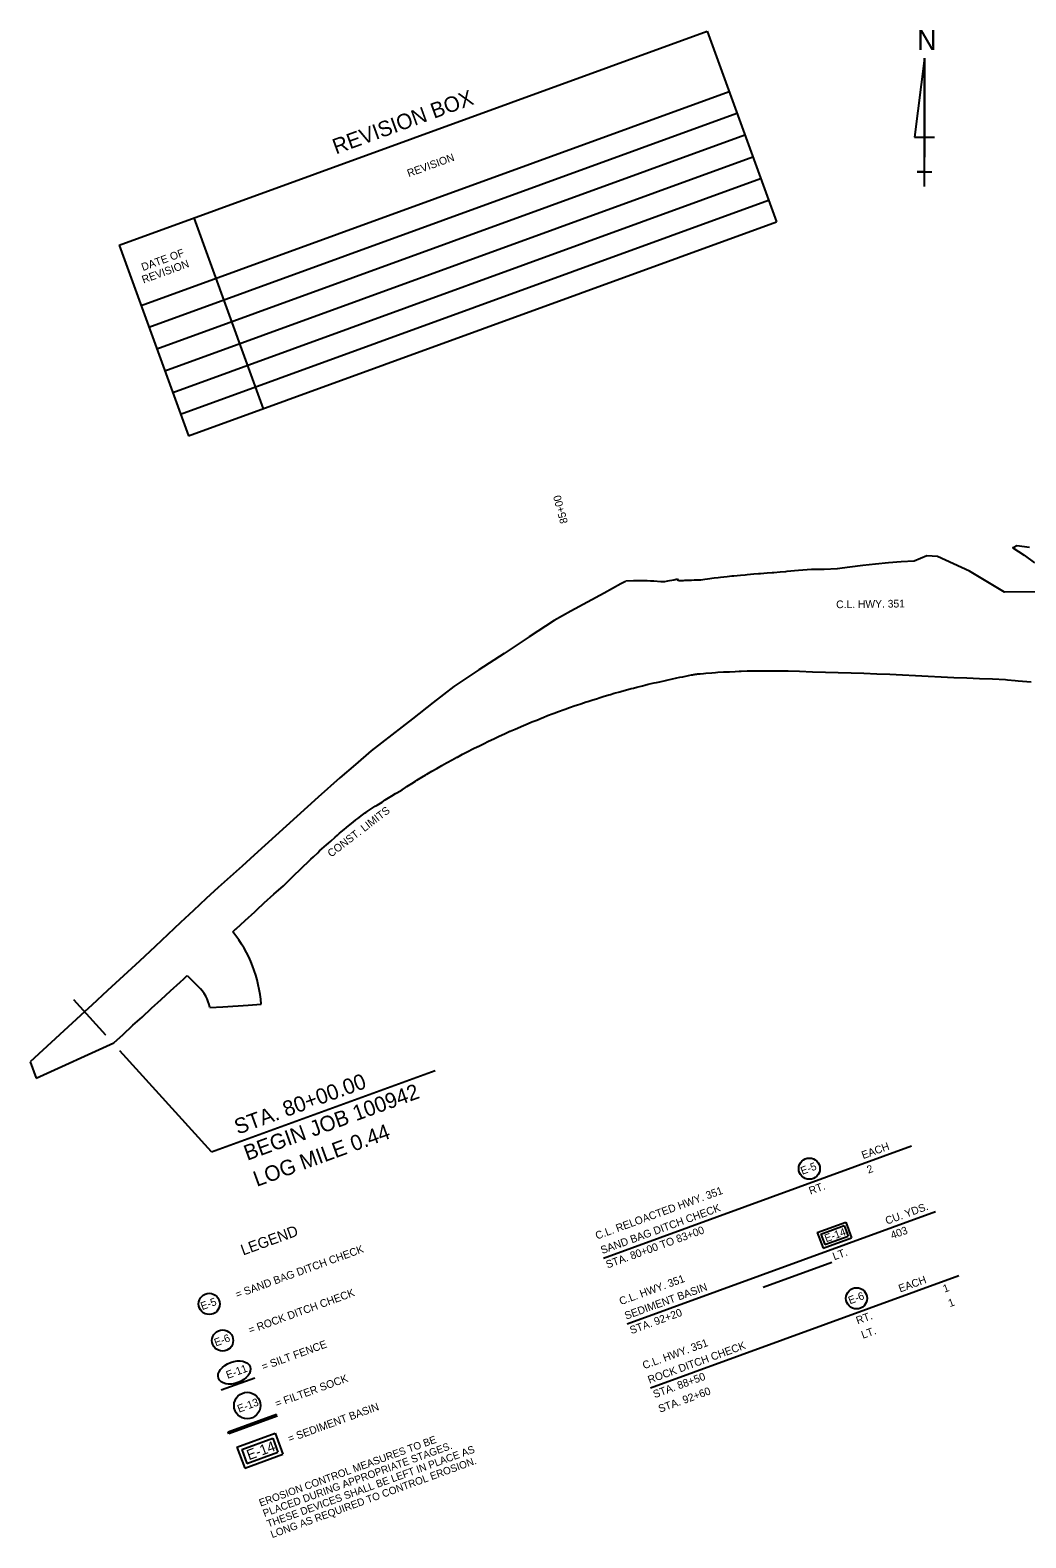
# Model space of a CAD drawing. Extents: x 1710803 to 1712425, y 548489 to 549912.
# Drawn here: x 1710803 to 1711577, y 548489 to 549662 of the extents above; entities that cross this region are included whole.
import ezdxf

# ---------------------------------------------------------------- set-up
doc = ezdxf.new("R2010")
doc.units = 0
for name, color, linetype in [('Default', 7, 'Continuous'), ('R_Contour Annot', 7, 'Continuous'), ('R_Contours', 7, 'Continuous'), ('R_Erosion', 7, 'Continuous'), ('R_Horz Alg', 7, 'Continuous'), ('R_Horz Alg Annot', 7, 'Continuous')]:
    doc.layers.add(name, color=color, linetype=linetype)

msp = doc.modelspace()

# ---------------------------------------------------------------- linework, layer by layer
at = {"layer": 'Default'}
msp.add_line((1711373, 548683.8), (1711426.2, 548703.2), dxfattribs=at)
at = {"layer": 'R_Contour Annot'}
for p, q in [((1711498.4, 549640), (1711490.7, 549578.4)), ((1711498.4, 549540), (1711498.4, 549640)), ((1711498.4, 549640), (1711498.4, 549563)), ((1711490.7, 549578.4), (1711506.1, 549578.4)), ((1711498.4, 549540), (1711498.4, 549563)), ((1711498.4, 549551.5), (1711492.7, 549551.5)), ((1711492.7, 549551.5), (1711504.2, 549551.5)), ((1711498.4, 549540), (1711498.4, 549551.5))]:
    msp.add_line(p, q, dxfattribs=at)
at = {"layer": 'R_Contours'}
for p, q in [((1710871.8, 549494.5), (1711329.2, 549661)), ((1711329.2, 549661), (1711383.3, 549512.5)), ((1710888.9, 549447.5), (1711346.3, 549614)), ((1710895, 549430.6), (1711352.5, 549597.1)), ((1710901.2, 549413.7), (1711358.6, 549580.2)), ((1710907.3, 549396.8), (1711364.8, 549563.3)), ((1710913.5, 549379.9), (1711370.9, 549546.4)), ((1710919.7, 549362.9), (1711377.1, 549529.4)), ((1710929.9, 549515.6), (1710983.9, 549367.2)), ((1710925.8, 549346), (1711383.3, 549512.5)), ((1710871.8, 549494.5), (1710925.8, 549346)), ((1710943.6, 548788.9), (1711117.8, 548852.3)), ((1711248.6, 548706.3), (1711488.4, 548793.6)), ((1711267.1, 548655.3), (1711507, 548742.6)), ((1711415, 548726.3), (1711437.2, 548734.4)), ((1711417.8, 548725), (1711435.9, 548731.6)), ((1711435.9, 548731.6), (1711438.9, 548723.4)), ((1711437.2, 548734.4), (1711441.7, 548722.1)), ((1711415, 548726.3), (1711419.5, 548714)), ((1711417.8, 548725), (1711420.8, 548716.8)), ((1711419.5, 548714), (1711441.7, 548722.1)), ((1711420.8, 548716.8), (1711438.9, 548723.4)), ((1711285.3, 548605.5), (1711525.1, 548692.8))]:
    msp.add_line(p, q, dxfattribs=at)
for points in [[(1710861.5, 548879.7), (1710836.5, 548907.3)], [(1710861.5, 548879.7), (1710861.5, 548879.7)], [(1710872.4, 548867.6), (1710872.4, 548867.6)], [(1710943.6, 548788.9), (1710872.4, 548867.6)]]:
    msp.add_lwpolyline(points, dxfattribs=at)
at = {"layer": 'R_Erosion'}
for p, q in [((1710956.7, 548571.1), (1710994.3, 548584.8)), ((1710994.8, 548583.4), (1710957.2, 548569.7)), ((1710965.5, 548572.7), (1710966.4, 548574.6)), ((1710966.8, 548573.2), (1710967.7, 548575.1)), ((1710968.1, 548573.7), (1710969, 548575.6)), ((1710969.5, 548574.1), (1710970.4, 548576.1)), ((1710970.8, 548574.6), (1710971.7, 548576.5)), ((1710972.1, 548575.1), (1710973, 548577)), ((1710973.5, 548575.6), (1710974.3, 548577.5)), ((1710974.8, 548576.1), (1710975.7, 548578)), ((1710976.1, 548576.6), (1710977, 548578.5)), ((1710977.4, 548577), (1710978.3, 548579)), ((1710978.8, 548577.5), (1710979.7, 548579.4)), ((1710980.1, 548578), (1710981, 548579.9)), ((1710981.4, 548578.5), (1710982.3, 548580.4)), ((1710982.8, 548579), (1710983.7, 548580.9)), ((1710984.1, 548579.5), (1710985, 548581.4)), ((1710985.4, 548579.9), (1710986.3, 548581.9)), ((1710986.7, 548580.4), (1710987.6, 548582.3)), ((1710988.1, 548580.9), (1710989, 548582.8)), ((1710989.4, 548581.4), (1710990.3, 548583.3)), ((1710990.7, 548581.9), (1710991.6, 548583.8)), ((1710992.1, 548582.4), (1710993, 548584.3)), ((1710993.4, 548582.8), (1710994.3, 548584.8)), ((1710994.7, 548583.3), (1710994.8, 548583.5)), ((1710957.2, 548569.7), (1710956.7, 548571.1)), ((1710956.8, 548570.7), (1710957.1, 548571.2)), ((1710957.5, 548569.8), (1710958.4, 548571.7)), ((1710958.8, 548570.3), (1710959.7, 548572.2)), ((1710960.2, 548570.7), (1710961.1, 548572.7)), ((1710961.5, 548571.2), (1710962.4, 548573.2)), ((1710962.8, 548571.7), (1710963.7, 548573.6)), ((1710963.5, 548559.3), (1710993.2, 548570.1)), ((1710964.1, 548572.2), (1710965, 548574.1)), ((1710967.3, 548557.5), (1710991.5, 548566.3)), ((1710991.5, 548566.3), (1710995.4, 548555.4)), ((1710993.2, 548570.1), (1710999.2, 548553.7)), ((1710963.5, 548559.3), (1710969.5, 548542.8)), ((1710967.3, 548557.5), (1710971.3, 548546.6)), ((1710969.5, 548542.8), (1710999.2, 548553.7)), ((1710971.3, 548546.6), (1710995.4, 548555.4))]:
    msp.add_line(p, q, dxfattribs=at)
msp.add_lwpolyline([(1710951.3, 548603.7), (1710977.5, 548613.2)], dxfattribs=at)
for centre, radius in [((1711408.8, 548775.9), 8.26), ((1711445.5, 548675), 8.26), ((1710941.9, 548670.7), 8.26), ((1710952.3, 548642.2), 8.26), ((1710971.5, 548591.6), 10.3)]:
    msp.add_circle(centre, radius, dxfattribs=at)
msp.add_ellipse((1710961.4, 548617.3), major_axis=(12.3, 4.5), ratio=0.638788, dxfattribs=at)
at = {"layer": 'R_Horz Alg'}
for p, q in [((1711500.2, 549252.7), (1711490.3, 549248.7)), ((1711307.1, 549233.3), (1711306.3, 549234.5)), ((1710924.8, 548926.2), (1710933.4, 548917.6)), ((1710952.4, 548901.9), (1710972.3, 548903.2)), ((1710972.3, 548903.2), (1710982.3, 548903.9)), ((1710942.4, 548901.2), (1710952.4, 548901.9))]:
    msp.add_line(p, q, dxfattribs=at)
for points in [[(1711580.2, 549259.3), (1711570.2, 549260.4), (1711567.8, 549259.1), (1711567.2, 549258.9), (1711576, 549253.3), (1711584, 549247.3)], [(1711490.3, 549248.7), (1711480.3, 549248.2), (1711470.3, 549247.2), (1711460.3, 549246.2), (1711450.3, 549245.1), (1711440.3, 549243.9), (1711430.4, 549242.6), (1711430.4, 549242.5), (1711420.4, 549242.1), (1711410.4, 549242.1), (1711400.4, 549241.2), (1711391.4, 549240.5), (1711390.3, 549240.4), (1711386.2, 549240), (1711381.1, 549239.6), (1711379.8, 549239.5), (1711375.9, 549239.2), (1711370.7, 549238.8), (1711369.3, 549238.7), (1711365.6, 549238.4), (1711360.4, 549237.9), (1711358.8, 549237.8), (1711355.3, 549237.4), (1711350.1, 549237), (1711348.4, 549236.8), (1711345, 549236.4), (1711339.8, 549235.9), (1711337.9, 549235.6), (1711334.7, 549235.3), (1711329.6, 549234.6), (1711327.5, 549234.3), (1711324.4, 549233.9), (1711319.3, 549233.7), (1711317, 549233.6), (1711314.1, 549233.5), (1711311.8, 549233.5), (1711310.7, 549233.4), (1711309.7, 549233.4), (1711308.9, 549233.4), (1711308.6, 549233.3), (1711308.2, 549233.3), (1711307.1, 549233.3)], [(1711610.6, 549225), (1711560.7, 549224.4), (1711533.5, 549240.8), (1711508.5, 549252.1), (1711500.2, 549252.7)], [(1711265.9, 549232.8), (1711262.2, 549230.9), (1711249.2, 549223.8), (1711236.3, 549216.7), (1711223.3, 549209.6), (1711210.3, 549202.5), (1711190.8, 549189.6), (1711171.3, 549176.8), (1711151.8, 549164), (1711132.3, 549151.1), (1711116.2, 549138.6), (1711100.1, 549126), (1711084.1, 549113.5), (1711068, 549100.9), (1711055.7, 549090.4), (1711043.5, 549079.9), (1711026.8, 549064.9), (1711010.1, 549049.9), (1710993.5, 549034.9), (1710976.8, 549019.9), (1710967.5, 549011.4), (1710958.2, 549003), (1710948.8, 548994.6), (1710939.5, 548986.2), (1710929.6, 548976.8), (1710919.7, 548967.5), (1710909.8, 548958.2), (1710899.9, 548948.8), (1710887.6, 548937.4), (1710875.3, 548926), (1710862.9, 548914.6), (1710850.6, 548903.2), (1710845.2, 548898.2)], [(1711306.3, 549234.5), (1711303.5, 549233.9), (1711298.5, 549232.9), (1711296, 549232.4), (1711293.2, 549232.6), (1711287.9, 549232.9), (1711285.1, 549233.1), (1711282.6, 549233.2), (1711277.2, 549233.4), (1711274.3, 549233.3), (1711272, 549233.2), (1711266.1, 549232.9)], [(1711319.3, 549160.5), (1711320, 549160.6), (1711320.9, 549160.7), (1711321.8, 549160.8), (1711323.8, 549160.9), (1711326.4, 549161.2), (1711328.4, 549161.4), (1711333, 549161.7), (1711335.7, 549161.9), (1711337.5, 549162.1), (1711342.1, 549162.4), (1711345, 549162.5), (1711346.7, 549162.6), (1711351.2, 549162.8), (1711354.3, 549163), (1711355.8, 549163), (1711360.4, 549163.2), (1711363.5, 549163.2), (1711364.9, 549163.3), (1711369.5, 549163.3), (1711372.8, 549163.3), (1711374, 549163.3), (1711378.6, 549163.3), (1711382.1, 549163.3), (1711383.2, 549163.3), (1711387.7, 549163.2), (1711391.3, 549163.2), (1711392.3, 549163.2), (1711401.2, 549162.9), (1711411.2, 549162.5), (1711421.3, 549162.1), (1711431.3, 549161.9), (1711431.3, 549161.9), (1711441.3, 549161.6), (1711451.3, 549161.4), (1711461.3, 549161), (1711471.3, 549160.6), (1711481.3, 549160.2), (1711491.3, 549159.6), (1711501.3, 549159.1), (1711511.3, 549158.7), (1711521.3, 549158.2), (1711531.3, 549157.7), (1711541.3, 549157.3), (1711551.3, 549157), (1711561.3, 549156.4), (1711563, 549156.3), (1711563, 549156.3), (1711569, 549155.7), (1711571.3, 549155.5), (1711581.3, 549154.7)], [(1710960.4, 548960.1), (1710962.6, 548962.4), (1710962.8, 548962.6), (1710970, 548969.1), (1710977.4, 548975.8), (1710978.9, 548977.2), (1710984.7, 548982.7), (1710992.2, 548989.4), (1710999.6, 548996), (1711006.8, 549003), (1711014, 549009.9), (1711019.7, 549015.4), (1711021.1, 549016.7), (1711023, 549018.5), (1711026.3, 549021.7), (1711027.8, 549023.1), (1711029.6, 549024.8), (1711033.1, 549027.8), (1711034.7, 549029.3), (1711036.5, 549030.8), (1711039.9, 549033.9), (1711041.7, 549035.4), (1711043.3, 549036.9), (1711046.8, 549039.9), (1711048.7, 549041.4), (1711050.3, 549042.7), (1711053.9, 549045.5), (1711056, 549047.2), (1711057.5, 549048.4), (1711061.1, 549051.1), (1711063.3, 549052.8), (1711063.7, 549053), (1711064.8, 549053.8), (1711068.7, 549056.3), (1711071.1, 549057.9), (1711072.5, 549058.7), (1711076.4, 549061.2), (1711078.9, 549063), (1711080.1, 549063.7), (1711084, 549066.1), (1711086.8, 549067.8), (1711088, 549068.4), (1711091.9, 549070.8), (1711094.7, 549072.6), (1711095.7, 549073.2), (1711099.6, 549075.7), (1711102.5, 549077.5), (1711103.4, 549078.1), (1711107.3, 549080.4), (1711110.4, 549082.3), (1711111.2, 549082.8), (1711115.1, 549085.1), (1711118.4, 549087), (1711119, 549087.4), (1711123, 549089.6), (1711126.4, 549091.6), (1711127, 549091.9), (1711131, 549094), (1711134.5, 549096), (1711135, 549096.2), (1711139, 549098.3), (1711142.7, 549100.3), (1711143, 549100.4), (1711147.1, 549102.5), (1711150.9, 549104.4), (1711151.1, 549104.5), (1711155.2, 549106.5), (1711159.2, 549108.5), (1711159.3, 549108.5), (1711163.4, 549110.4), (1711167.5, 549112.3), (1711167.6, 549112.4), (1711171.7, 549114.3), (1711175.8, 549116.2), (1711176, 549116.2), (1711180, 549118), (1711184.2, 549119.8), (1711184.5, 549119.9), (1711188.3, 549121.5), (1711192.5, 549123.3), (1711193, 549123.5), (1711196.7, 549125), (1711201, 549126.7), (1711201.6, 549127), (1711205.2, 549128.4), (1711209.5, 549130.1), (1711210.2, 549130.3), (1711213.7, 549131.6), (1711218, 549133.2), (1711218.9, 549133.5), (1711222.3, 549134.7), (1711226.6, 549136.2), (1711227.6, 549136.5), (1711230.9, 549137.7), (1711235.2, 549139.1), (1711236.4, 549139.5), (1711239.6, 549140.5), (1711243.9, 549141.8), (1711245.2, 549142.2), (1711248.3, 549143.2), (1711252.7, 549144.5), (1711254.1, 549144.9), (1711257, 549145.8), (1711261.4, 549147), (1711263, 549147.5), (1711265.8, 549148.2), (1711270.2, 549149.4), (1711271.9, 549149.9), (1711274.6, 549150.5), (1711279.1, 549151.7), (1711280.9, 549152.1), (1711283.5, 549152.8), (1711288, 549153.8), (1711290, 549154.3), (1711292.4, 549154.8), (1711296.9, 549155.8), (1711299, 549156.3), (1711301.3, 549156.8), (1711305.8, 549157.8), (1711308.1, 549158.3), (1711310.3, 549158.7), (1711314.8, 549159.6), (1711317.2, 549160.1), (1711317.8, 549160.2), (1711318.7, 549160.4), (1711319, 549160.4), (1711319.3, 549160.5)], [(1710867.6, 548873.7), (1710867.6, 548873.7), (1710875, 548880.4), (1710882.3, 548887.2), (1710882.6, 548887.5), (1710889.7, 548893.9), (1710897.1, 548900.7), (1710904.5, 548907.5), (1710911.8, 548914.2), (1710919.2, 548921), (1710922.1, 548923.7), (1710923.6, 548925.1), (1710924.8, 548926.2)], [(1710845.2, 548898.2), (1710802.6, 548859)], [(1710807.2, 548846.4), (1710867.6, 548873.7)], [(1710802.6, 548859), (1710807.2, 548846.4)]]:
    msp.add_lwpolyline(points, dxfattribs=at)
for centre, radius, start, end in [((1710882.5, 548897.3), 100, 3.7733, 38.8727), ((1710913.9, 548896.3), 28.8, 9.8067, 47.5701)]:
    msp.add_arc(centre, radius, start, end, dxfattribs=at)

# ---------------------------------------------------------------- texts
at = {"layer": 'R_Contour Annot'}
msp.add_text('N', height=15.4, dxfattribs=at).set_placement((1711492.8, 549646.4))
at = {"layer": 'R_Contours'}
for s, height, rotation, p in [('REVISION BOX', 12, 20, (1711040.5, 549565)), ('REVISION', 6, 20, (1711097.2, 549547.3)), ('DATE OF', 6, 20, (1710890.4, 549474.3)), ('REVISION', 6, 20, (1710890.8, 549464.6)), ('C.L. HWY. 351', 6, 0.6428, (1711429.7, 549212)), ('CONST. LIMITS', 6, 37.5007, (1711036.8, 549017.9)), ('STA. 80+00.00', 12, 20, (1710964.1, 548802.3)), ('BEGIN JOB 100942', 12, 20, (1710971.5, 548782)), ('LOG MILE 0.44', 12, 20, (1710978.9, 548761.7)), ('EACH', 6, 20, (1711450.7, 548783.3)), ('2', 6, 20, (1711454.8, 548772)), ('RT.', 6, 20, (1711409.7, 548755.6)), ('C.L. RELOACTED HWY. 351', 6, 20, (1711243.6, 548720.7)), ('SAND BAG DITCH CHECK', 6, 20, (1711247.7, 548709.4)), ('CU. YDS.', 6, 20, (1711469.2, 548732.3)), ('STA. 80+00 TO 83+00', 6, 20, (1711251.8, 548698.2)), ('E-14', 6, 19.9884, (1711421.9, 548718.6)), ('403', 6, 20, (1711473.3, 548721)), ('LT.', 6, 20, (1711428.2, 548704.6)), ('C.L. HWY. 351', 6, 20, (1711262.2, 548669.7)), ('       EACH', 6, 20, (1711464.8, 548674.2)), ('SEDIMENT BASIN', 6, 20, (1711266.3, 548658.4)), ('1', 6, 20, (1711514, 548679.4)), ('1', 6, 20, (1711518.1, 548668.1)), ('STA. 92+20', 6, 20, (1711270.4, 548647.1)), ('RT.', 6, 20, (1711446.4, 548654.7)), ('LT. ', 6, 20, (1711450.5, 548643.5)), ('C.L. HWY. 351', 6, 20, (1711280.3, 548619.8)), ('ROCK DITCH CHECK', 6, 20, (1711284.4, 548608.6)), ('STA. 88+50', 6, 20, (1711288.5, 548597.3)), ('STA. 92+60', 6, 20, (1711292.6, 548586))]:
    msp.add_text(s, height=height, rotation=rotation, dxfattribs=at).set_placement(p)
at = {"layer": 'R_Erosion'}
for s, height, rotation, p in [('E-5 ', 6, 20.4005, (1711403.3, 548771.1)), ('LEGEND', 8.44, 20, (1710968.3, 548708.3)), ('= SAND BAG DITCH CHECK', 6, 20, (1710963.6, 548675)), ('= ROCK DITCH CHECK', 6, 20, (1710973.7, 548647.3)), ('E-5 ', 6, 20, (1710936.5, 548665.8)), ('E-6 ', 6, 20.4005, (1711440.4, 548670.3)), ('E-6 ', 6, 20.4005, (1710947.1, 548637.5)), ('= SILT FENCE', 6, 20, (1710984, 548618.8)), ('E-11', 6, 20.2144, (1710956.3, 548612.3)), ('= FILTER SOCK', 6, 20, (1710994.5, 548590.1)), ('E-13', 6, 20.4005, (1710965.1, 548586)), ('= SEDIMENT BASIN', 6, 20, (1711004.4, 548562.8)), ('E-14', 8, 19.9884, (1710972.8, 548549)), ('EROSION CONTROL MEASURES TO BE', 5.769, 20, (1710981.9, 548512.9)), ('PLACED DURING APPROPRIATE STAGES. ', 5.769, 20, (1710984.9, 548504.8)), ('THESE DEVICES SHALL BE LEFT IN PLACE AS ', 5.769, 20, (1710987.9, 548496.6)), ('LONG AS REQUIRED TO CONTROL EROSION.', 5.769, 20, (1710990.9, 548488.4))]:
    msp.add_text(s, height=height, rotation=rotation, dxfattribs=at).set_placement(p)
at = {"layer": 'R_Horz Alg Annot'}
msp.add_text('85+00', height=6, rotation=104.9919, dxfattribs=at).set_placement((1711221, 549278.7))

doc.saveas('drawing.dxf')
